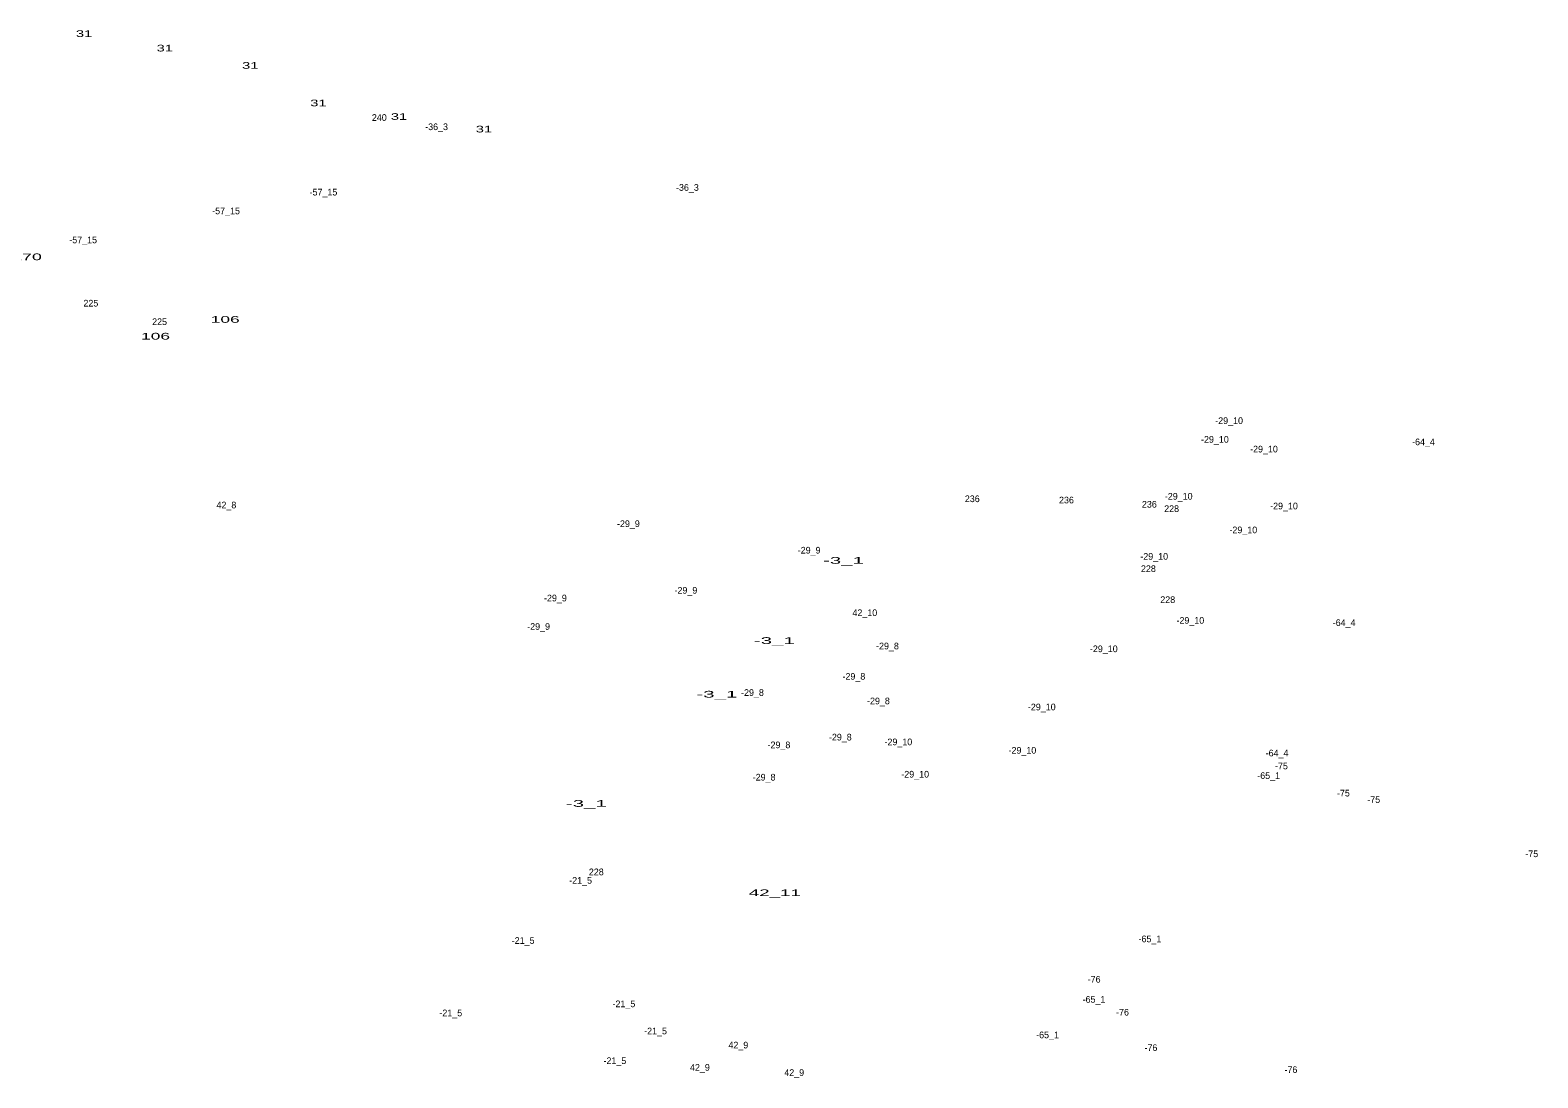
# Model space of a CAD drawing. Extents: x -656096 to -652763, y -1002270 to -998958.
# Drawn here: x -654064 to -653159, y -1000356 to -999727 of the extents above; entities that cross this region are included whole.
import ezdxf
from ezdxf.enums import TextEntityAlignment as Align

# ---------------------------------------------------------------- set-up
doc = ezdxf.new("R2010")
doc.units = 0
doc.header["$LTSCALE"] = 1.6
doc.layers.add('24', color=7, linetype='Continuous')

msp = doc.modelspace()

# ---------------------------------------------------------------- texts
at = {"layer": '24'}
for s, width, p in [('31', 1.65, (-654031.177, -999731.46)), ('31', 1.65, (-653982.717, -999740.18)), ('31', 1.65, (-653931.417, -999750.58)), ('31', 1.65, (-653890.507, -999773.07)), ('31', 1.65, (-653842.137, -999781.22)), ('31', 1.65, (-653791.157, -999788.78)), ('170', 2, (-654065.429, -999865.43)), ('106', 1.95, (-653946.449, -999902.99)), ('106', 1.95, (-653988.269, -999913.06)), ('-3_1', 2.3, (-653575.351, -1000047.6)), ('-3_1', 2.3, (-653616.841, -1000095.7)), ('-3_1', 2.3, (-653651.341, -1000127.89)), ('-3_1', 2.3, (-653729.671, -1000193.45)), ('42_11', 2.1, (-653616.551, -1000247.05))]:
    msp.add_text(s, height=4, dxfattribs=dict(at, width=width)).set_placement(p, align=Align.CENTER)
for s, p in [('240', (-653853.955, -999781.84)), ('-36_3', (-653819.578, -999787.38)), ('-57_15', (-653887.472, -999826.6)), ('-36_3', (-653669.028, -999823.8)), ('-57_15', (-653945.942, -999837.86)), ('-57_15', (-654031.722, -999855.26)), ('225', (-654027.097, -999893.24)), ('225', (-653985.857, -999904.38)), ('-29_10', (-653343.856, -999963.74)), ('-29_10', (-653352.386, -999974.99)), ('-29_10', (-653322.926, -999980.81)), ('-64_4', (-653227.176, -999976.47)), ('236', (-653498.033, -1000010.62)), ('236', (-653441.493, -1000011.39)), ('-29_10', (-653374.106, -1000009.12)), ('42_8', (-653945.74, -1000014.37)), ('236', (-653391.733, -1000013.91)), ('228', (-653378.367, -1000016.54)), ('-29_10', (-653310.906, -1000014.94)), ('-29_9', (-653704.433, -1000025.58)), ('-29_10', (-653335.326, -1000029.29)), ('-29_9', (-653595.943, -1000041.48)), ('-29_10', (-653388.836, -1000045.2)), ('228', (-653392.307, -1000052.57)), ('-29_9', (-653669.923, -1000065.53)), ('-29_9', (-653748.253, -1000070.18)), ('228', (-653380.697, -1000071.16)), ('42_10', (-653562.517, -1000079.01)), ('-29_10', (-653367.126, -1000083.6)), ('-29_9', (-653758.333, -1000087.25)), ('-64_4', (-653274.816, -1000084.95)), ('-29_8', (-653548.928, -1000098.96)), ('-29_10', (-653419.076, -1000100.66)), ('-29_8', (-653569.088, -1000117.19)), ('-29_8', (-653629.958, -1000126.89)), ('-29_8', (-653554.348, -1000131.93)), ('-29_10', (-653456.306, -1000135.57)), ('-29_8', (-653577.228, -1000153.65)), ('-29_10', (-653542.386, -1000156.52)), ('-29_8', (-653614.068, -1000158.31)), ('-29_10', (-653467.936, -1000161.56)), ('-64_4', (-653315.086, -1000163.2)), ('-75', (-653312.441, -1000170.97)), ('-29_8', (-653622.978, -1000177.7)), ('-29_10', (-653532.296, -1000175.91)), ('-65_1', (-653320.122, -1000176.73)), ('-75', (-653275.261, -1000187.25)), ('-75', (-653257.061, -1000191.12)), ('-75', (-653162.181, -1000223.66)), ('228', (-653723.697, -1000234.52)), ('-21_5', (-653733.116, -1000239.63)), ('-65_1', (-653391.382, -1000274.74)), ('-21_5', (-653767.626, -1000275.7)), ('-76', (-653424.885, -1000298.99)), ('-21_5', (-653811.056, -1000319.15)), ('-21_5', (-653707.136, -1000313.71)), ('-65_1', (-653424.962, -1000311.03)), ('-76', (-653407.845, -1000318.74)), ('-21_5', (-653688.146, -1000330.01)), ('-65_1', (-653452.842, -1000332.34)), ('42_9', (-653638.444, -1000338.46)), ('-76', (-653390.805, -1000340.05)), ('-21_5', (-653712.566, -1000347.85)), ('42_9', (-653661.514, -1000351.84)), ('42_9', (-653604.904, -1000354.95)), ('-76', (-653306.765, -1000353.22))]:
    msp.add_text(s, height=4, dxfattribs=at).set_placement(p, align=Align.CENTER)

doc.saveas('drawing.dxf')
